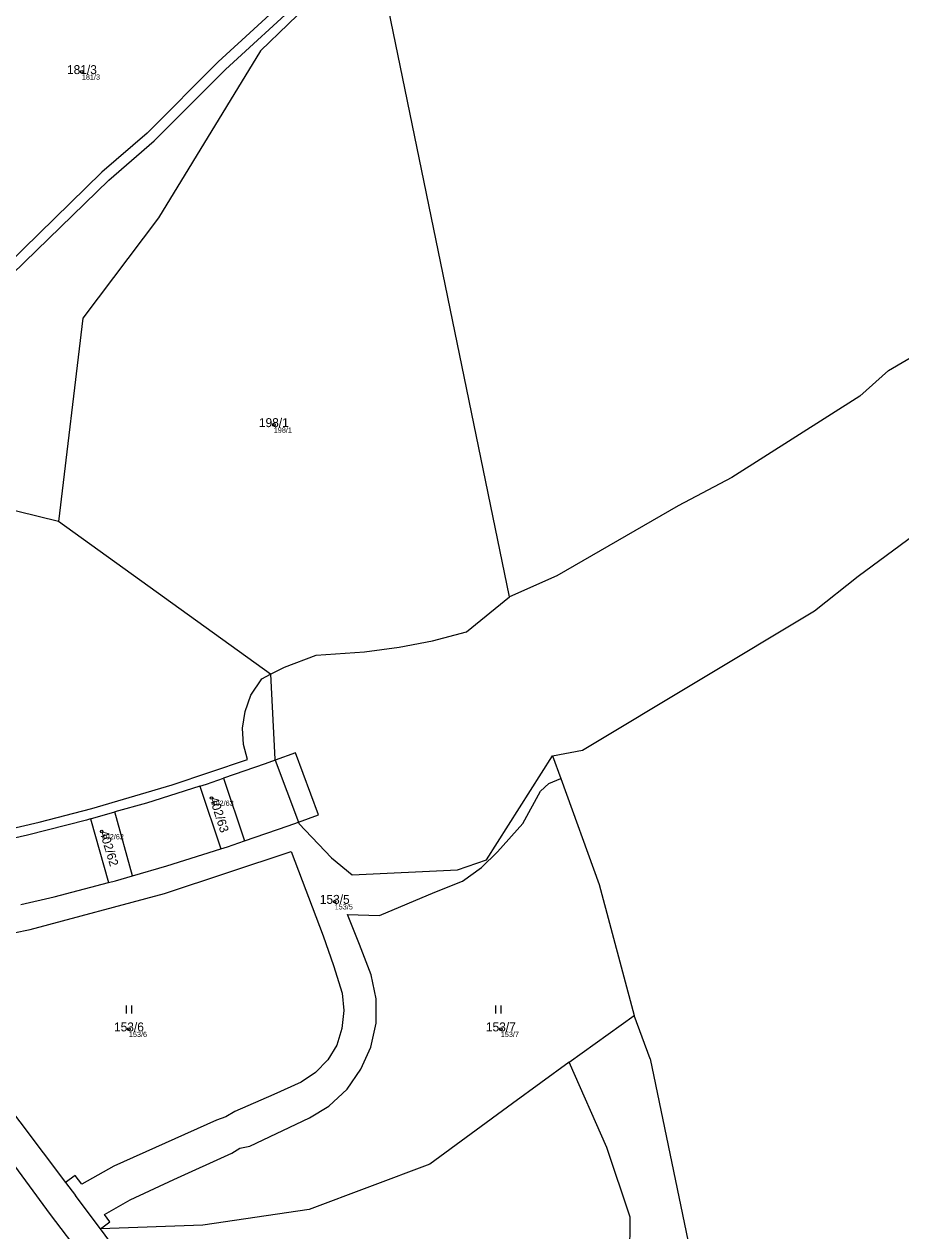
# Model space of a CAD drawing. Extents: x -868010 to -864567, y -1041968 to -1040406.
# Drawn here: x -866905.6 to -866738.8, y -1041242.1 to -1041012.6 of the extents above; entities that cross this region are included whole.
import ezdxf

# ---------------------------------------------------------------- set-up
doc = ezdxf.new("R2010")
doc.units = 0
for name, color, linetype in [('Definiční body', 7, 'Continuous'), ('Hranice parcel', 7, 'Continuous'), ('Parcelní čísla', 7, 'Continuous'), ('Vnitřní kresba', 7, 'Continuous'), ('Věcná břemena k části', 7, 'Continuous'), ('Značky kultur', 7, 'Continuous')]:
    doc.layers.add(name, color=color, linetype=linetype)

msp = doc.modelspace()

# ---------------------------------------------------------------- linework, layer by layer
at = {"layer": 'Definiční body'}
for centre in [(-866894.64, -1041021.67994), (-866858.12, -1041088.82994), (-866869.97, -1041159.80994), (-866890.87, -1041166.18994), (-866846.53, -1041179.51994), (-866885.69, -1041203.77994), (-866814.92, -1041203.77994)]:
    msp.add_circle(centre, 0.25, dxfattribs=at)
at = {"layer": 'Hranice parcel'}
for p, q in [((-866838.97, -1040996.77), (-866860.65, -1041017.67)), ((-866813.25, -1041121.55), (-866838.97, -1040996.77)), ((-866860.65, -1041017.67), (-866880.04, -1041049.45)), ((-866880.04, -1041049.45), (-866894.47, -1041068.52)), ((-866894.47, -1041068.52), (-866899.09, -1041107.19)), ((-866899.09, -1041107.19), (-866930.4, -1041099.56)), ((-866858.72, -1041136.28), (-866899.09, -1041107.19)), ((-866821.42, -1041128.23), (-866813.25, -1041121.55)), ((-866827.91, -1041129.89), (-866821.42, -1041128.23)), ((-866840.88, -1041131.98), (-866834.23, -1041131.1)), ((-866834.23, -1041131.1), (-866827.91, -1041129.89)), ((-866856.05, -1041134.9), (-866850.07, -1041132.62)), ((-866850.07, -1041132.62), (-866840.88, -1041131.98)), ((-866858.72, -1041136.28), (-866856.05, -1041134.9)), ((-866862.46, -1041140.24), (-866860.42, -1041137.16)), ((-866860.42, -1041137.16), (-866858.72, -1041136.28)), ((-866858.72, -1041136.28), (-866857.91, -1041152.45)), ((-866863.58, -1041143.36), (-866862.46, -1041140.24)), ((-866864.05, -1041146.51), (-866863.58, -1041143.36)), ((-866863.89, -1041149.62), (-866864.05, -1041146.51)), ((-866863.09, -1041152.51), (-866863.89, -1041149.62)), ((-866817.62, -1041171.57), (-866805.1, -1041151.77)), ((-866805.1, -1041151.77), (-866799.4, -1041150.72)), ((-866805.1, -1041151.77), (-866803.52, -1041156.12)), ((-866877.45, -1041157.28), (-866863.09, -1041152.51)), ((-866857.91, -1041152.45), (-866857.85, -1041152.62)), ((-866857.85, -1041152.62), (-866853.44, -1041164.4)), ((-866870.95, -1041157.19), (-866867.66, -1041156.05)), ((-866867.66, -1041156.05), (-866863.69, -1041167.97)), ((-866805.79, -1041157.05), (-866803.52, -1041156.12)), ((-866803.52, -1041156.12), (-866796.2, -1041176.25)), ((-866892.77, -1041161.78), (-866877.45, -1041157.28)), ((-866872.19, -1041157.58), (-866870.95, -1041157.19)), ((-866872.19, -1041157.58), (-866868.22, -1041169.49)), ((-866810.75, -1041164.69), (-866807.36, -1041158.52)), ((-866807.36, -1041158.52), (-866805.79, -1041157.05)), ((-866902.75, -1041164.39), (-866892.77, -1041161.78)), ((-866893, -1041163.79), (-866888.35, -1041162.47)), ((-866884.98, -1041174.61), (-866888.35, -1041162.47)), ((-866917.35, -1041167.76), (-866902.75, -1041164.39)), ((-866893, -1041163.79), (-866889.58, -1041175.91)), ((-866853.44, -1041164.4), (-866853.35, -1041164.63)), ((-866853.35, -1041164.63), (-866847.14, -1041171.18)), ((-866815.55, -1041170.07), (-866810.75, -1041164.69)), ((-866878.92, -1041177.96), (-866854.81, -1041169.97)), ((-866868.22, -1041169.49), (-866866.94, -1041169.09)), ((-866866.94, -1041169.09), (-866863.69, -1041167.97)), ((-866854.81, -1041169.97), (-866848.71, -1041186)), ((-866818.61, -1041173.06), (-866815.55, -1041170.07)), ((-866847.14, -1041171.18), (-866843.18, -1041174.41)), ((-866823.18, -1041173.49), (-866817.62, -1041171.57)), ((-866888.26, -1041175.56), (-866884.98, -1041174.61)), ((-866843.18, -1041174.41), (-866823.18, -1041173.49)), ((-866822.18, -1041175.6), (-866818.61, -1041173.06)), ((-866889.58, -1041175.91), (-866888.26, -1041175.56)), ((-866827.45, -1041177.75), (-866822.18, -1041175.6)), ((-866796.2, -1041176.25), (-866789.54, -1041201.18)), ((-866904.46, -1041184.83), (-866878.92, -1041177.96)), ((-866838.03, -1041182.15), (-866827.45, -1041177.75)), ((-866841.82, -1041187.65), (-866844.12, -1041181.97)), ((-866844.12, -1041181.97), (-866838.03, -1041182.15)), ((-866930.14, -1041190.03), (-866904.46, -1041184.83)), ((-866848.71, -1041186), (-866846.73, -1041191.67)), ((-866839.6, -1041193.45), (-866841.82, -1041187.65)), ((-866928.98, -1041191.57), (-866897.74, -1041232.98)), ((-866846.73, -1041191.67), (-866845.08, -1041196.94)), ((-866838.62, -1041197.99), (-866839.6, -1041193.45)), ((-866900.58, -1041239.05), (-866932.62, -1041195.63)), ((-866845.08, -1041196.94), (-866844.79, -1041200.26)), ((-866838.63, -1041202.64), (-866838.62, -1041197.99)), ((-866844.79, -1041200.26), (-866845.16, -1041203.64)), ((-866801.89, -1041210.04), (-866789.54, -1041201.18)), ((-866786.48, -1041209.4), (-866789.54, -1041201.18)), ((-866845.16, -1041203.64), (-866846.15, -1041206.81)), ((-866839.64, -1041207.21), (-866838.63, -1041202.64)), ((-866846.15, -1041206.81), (-866847.83, -1041209.61)), ((-866841.53, -1041211.38), (-866839.64, -1041207.21)), ((-866847.83, -1041209.61), (-866850.15, -1041212.01)), ((-866844.18, -1041215.21), (-866841.53, -1041211.38)), ((-866801.89, -1041210.04), (-866812.68, -1041217.89)), ((-866794.74, -1041226.26), (-866801.89, -1041210.04)), ((-866786.48, -1041209.4), (-866767.3, -1041301.64)), ((-866850.15, -1041212.01), (-866852.89, -1041213.88)), ((-866852.89, -1041213.88), (-866858.1, -1041216.2)), ((-866847.62, -1041218.41), (-866844.18, -1041215.21)), ((-866858.1, -1041216.2), (-866865.55, -1041219.44)), ((-866851.31, -1041220.64), (-866847.62, -1041218.41)), ((-866812.68, -1041217.89), (-866828.44, -1041229.44)), ((-866867.23, -1041220.45), (-866869, -1041221.09)), ((-866865.55, -1041219.44), (-866867.23, -1041220.45)), ((-866862.69, -1041226.03), (-866851.31, -1041220.64)), ((-866869, -1041221.09), (-866888.57, -1041229.82)), ((-866877.12, -1041232.41), (-866866.11, -1041227.34)), ((-866866.11, -1041227.34), (-866864.6, -1041226.41)), ((-866864.6, -1041226.41), (-866862.69, -1041226.03)), ((-866790.27, -1041239.55), (-866794.74, -1041226.26)), ((-866888.57, -1041229.82), (-866894.67, -1041233.28)), ((-866828.44, -1041229.44), (-866851.4, -1041238.06)), ((-866895.93, -1041231.61), (-866897.74, -1041232.98)), ((-866894.67, -1041233.28), (-866895.93, -1041231.61)), ((-866897.74, -1041232.98), (-866895.88, -1041235.44)), ((-866885.44, -1041236.24), (-866877.12, -1041232.41)), ((-866894.03, -1041237.89), (-866895.88, -1041235.44)), ((-866890.31, -1041239.05), (-866885.44, -1041236.24)), ((-866849.19, -1041306.79), (-866900.58, -1041239.05)), ((-866891.09, -1041241.79), (-866894.03, -1041237.89)), ((-866889.29, -1041240.4), (-866890.31, -1041239.05)), ((-866851.4, -1041238.06), (-866871.59, -1041241.07)), ((-866891.09, -1041241.79), (-866889.29, -1041240.4)), ((-866871.59, -1041241.07), (-866891.09, -1041241.79)), ((-866790.52, -1041258.58), (-866790.27, -1041239.55)), ((-866843.74, -1041305.21), (-866891.09, -1041241.79))]:
    msp.add_line(p, q, dxfattribs=at)
for points in [[(-866746.58, -1041083.36), (-866741.14, -1041078.5), (-866729.98, -1041071.97), (-866713.38, -1041061.19), (-866699.19, -1041050.74), (-866680.85, -1041036.62), (-866665.59, -1041025.37), (-866658.83, -1041020.09)], [(-866746.58, -1041083.36), (-866770.97, -1041098.86), (-866781.19, -1041104.26), (-866804.23, -1041117.57), (-866813.25, -1041121.55)], [(-866746.91, -1041117.59), (-866730.92, -1041105.82), (-866709.61, -1041088.65)], [(-866799.4, -1041150.72), (-866755.21, -1041124.2), (-866746.91, -1041117.59)]]:
    msp.add_lwpolyline(points, dxfattribs=at)
at = {"layer": 'Vnitřní kresba'}
for p, q in [((-866854, -1041151.2), (-866857.85, -1041152.62)), ((-866849.61, -1041163), (-866854, -1041151.2)), ((-866859.74, -1041153.32), (-866867.66, -1041156.05)), ((-866857.85, -1041152.62), (-866859.74, -1041153.32)), ((-866872.19, -1041157.58), (-866882.36, -1041160.77)), ((-866882.36, -1041160.77), (-866888.35, -1041162.47)), ((-866853.44, -1041164.4), (-866849.61, -1041163)), ((-866893.76, -1041164.01), (-866905, -1041166.89)), ((-866893, -1041163.79), (-866893.76, -1041164.01)), ((-866863.69, -1041167.97), (-866855.37, -1041165.11)), ((-866855.37, -1041165.11), (-866853.44, -1041164.4)), ((-866905, -1041166.89), (-866909.15, -1041167.84)), ((-866878.47, -1041172.72), (-866868.22, -1041169.49)), ((-866884.98, -1041174.61), (-866878.47, -1041172.72)), ((-866899.93, -1041178.61), (-866889.58, -1041175.91)), ((-866906.26, -1041180.09), (-866899.93, -1041178.61))]:
    msp.add_line(p, q, dxfattribs=at)
at = {"layer": 'Věcná břemena k části'}
for points in [[(-866854.38, -1041006.6), (-866868.68, -1041019.76), (-866882.22, -1041033.36), (-866890.82, -1041040.78), (-866911.84, -1041061.21), (-866913.99, -1041066.06), (-866924.08, -1041076.56), (-866928.61, -1041079.8), (-866930.84, -1041081.06), (-866932.53, -1041081.42), (-866939.75, -1041081.81), (-866942.88, -1041083.13), (-866946.55, -1041086.11), (-866965.25, -1041102.99), (-866967.63, -1041104.22), (-866983.14, -1041118.72), (-866991.28, -1041127.71), (-866999.65, -1041137.89), (-867013.79, -1041153.08), (-867024.92, -1041166.14)], [(-866910.16, -1041062.37), (-866889.48, -1041042.26), (-866880.86, -1041034.82), (-866867.3, -1041021.22), (-866852.92, -1041007.96)]]:
    msp.add_lwpolyline(points, dxfattribs=at)
at = {"layer": 'Značky kultur'}
for p, q in [((-866886.141, -1041200.79), (-866886.141, -1041199.29)), ((-866885.14, -1041200.79), (-866885.14, -1041199.29)), ((-866815.861, -1041200.79), (-866815.861, -1041199.29)), ((-866814.86, -1041200.79), (-866814.86, -1041199.29))]:
    msp.add_line(p, q, dxfattribs=at)

# ---------------------------------------------------------------- texts
at = {"layer": 'Definiční body'}
for s, p in [('181/3', (-866894.64, -1041023.169)), ('198/1', (-866858.12, -1041090.319)), ('402/63', (-866869.97, -1041161.299)), ('402/62', (-866890.87, -1041167.679)), ('153/5', (-866846.53, -1041181.009)), ('153/6', (-866885.69, -1041205.269)), ('153/7', (-866814.92, -1041205.269))]:
    msp.add_text(s, height=0.999996, dxfattribs=at).set_placement(p)
at = {"layer": 'Parcelní čísla'}
for s, p in [('181/3', (-866897.476, -1041022.105)), ('198/1', (-866860.956, -1041089.255)), ('153/5', (-866849.366, -1041179.945)), ('153/6', (-866888.526, -1041204.205)), ('153/7', (-866817.756, -1041204.205))]:
    msp.add_text(s, height=1.699998, dxfattribs=at).set_placement(p)
for s, rotation, p in [('402/63', 288, (-866870.374, -1041159.941)), ('402/62', 287, (-866891.276, -1041166.314))]:
    msp.add_text(s, height=1.699998, rotation=rotation, dxfattribs=at).set_placement(p)

doc.saveas('drawing.dxf')
